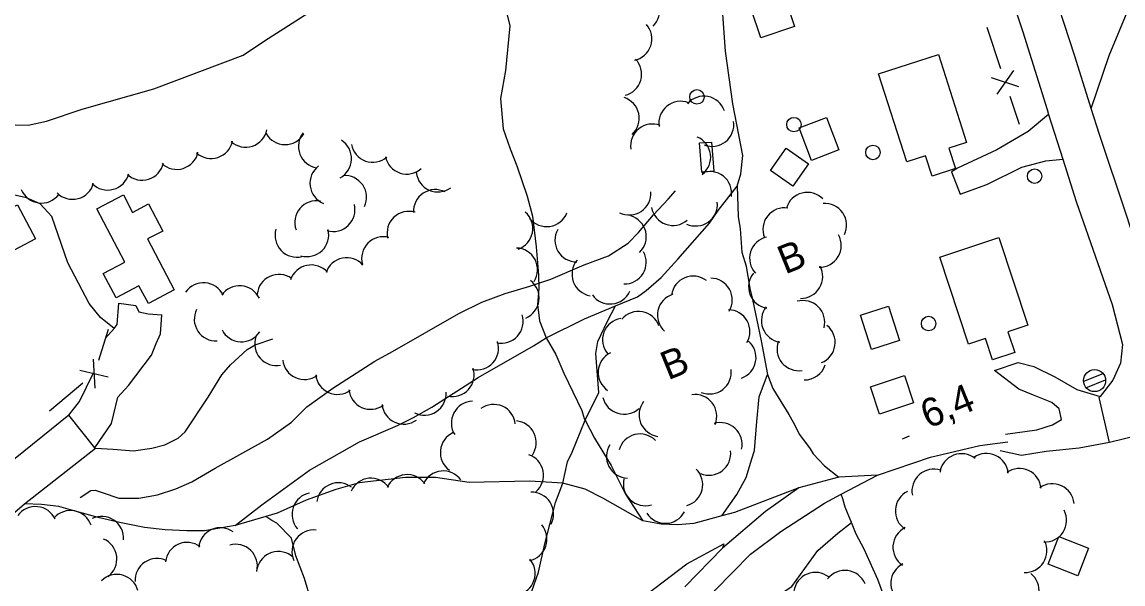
# Model space of a CAD drawing. Extents: x 362852 to 366875, y 5563573 to 5566479.
# Drawn here: x 363726 to 363877.7, y 5565014.1 to 5565091.6 of the extents above; entities that cross this region are included whole.
import ezdxf

# ---------------------------------------------------------------- set-up
doc = ezdxf.new("R2010")
doc.units = 0
for name, color, linetype in [('Niveau 19', 7, 'Continuous'), ('Niveau 2', 7, 'Continuous'), ('Niveau 21', 7, 'Continuous'), ('Niveau 22', 7, 'Continuous'), ('Niveau 3', 7, 'Continuous'), ('Niveau 31', 7, 'Continuous'), ('Niveau 36', 7, 'Continuous'), ('Niveau 37', 7, 'Continuous'), ('Niveau 4', 7, 'Continuous'), ('Niveau 44', 7, 'Continuous')]:
    doc.layers.add(name, color=color, linetype=linetype)

msp = doc.modelspace()

# ---------------------------------------------------------------- linework, layer by layer
at = {"layer": 'Niveau 19'}
for points in [[(363867.43, 5565078.84), (363864.61, 5565076.48), (363860.28, 5565073.95), (363854.89, 5565071.45), (363854.05, 5565070.96), (363855.26, 5565067.86), (363858.91, 5565069.2), (363863.75, 5565071.56), (363867.05, 5565072.44), (363869.37, 5565072.68)], [(363737.49, 5565048.02), (363738.66, 5565049.36), (363739.11, 5565049.87), (363739.34, 5565052.82), (363741.65, 5565052.52), (363742.08, 5565051.63), (363743.37, 5565051.35), (363745.23, 5565051.23)], [(363736.04, 5565032.91), (363738.31, 5565036.25), (363739.2, 5565039.87), (363740.66, 5565041.5), (363743.83, 5565045.65), (363744.47, 5565047.29), (363745.06, 5565048.6), (363745.23, 5565051.23)], [(363861.5, 5565034.77), (363865.81, 5565035.35), (363867.96, 5565036.04), (363869.21, 5565036.81), (363868.9, 5565038.28), (363867.86, 5565039.16), (363865.34, 5565040.13), (363863.31, 5565040.98), (363859.96, 5565043.55), (363863.25, 5565044.65), (363865.38, 5565044.12), (363868.3, 5565042.66), (363871.33, 5565040.93), (363874.52, 5565039.95)], [(363732.42, 5565037.4), (363733.9, 5565039.29), (363735.84, 5565043.22)], [(363875.8, 5565033.63), (363871.63, 5565032.86), (363867.09, 5565032.37), (363863.69, 5565031.85), (363860.75, 5565032.46)]]:
    msp.add_lwpolyline(points, dxfattribs=at)
at = {"layer": 'Niveau 2'}
msp.add_lwpolyline([(363717.82, 5565077.58), (363726.82, 5565077.39), (363729.35, 5565077.93), (363734.29, 5565079.58), (363744.13, 5565082.37), (363756.45, 5565087.04), (363759.39, 5565089), (363767, 5565093.88)], dxfattribs=at)
at = {"layer": 'Niveau 21'}
msp.add_line((363736.04, 5565032.91), (363732.42, 5565037.4), dxfattribs=at)
for points in [[(363894.37, 5565204.95), (363891.04, 5565200.97), (363888.24, 5565197.21), (363884.39, 5565191.81), (363881.5, 5565187.79), (363876.28, 5565178.61), (363871.48, 5565169.6), (363867.57, 5565160.54), (363864.93, 5565154.01), (363864.35, 5565152.4), (363861.97, 5565145.76), (363861.32, 5565143.93), (363859.06, 5565135.24), (363857.7, 5565126.8), (363857.47, 5565121.97), (363857.33, 5565119.17), (363857.74, 5565112.52), (363858.63, 5565107.47), (363859.14, 5565105.67), (363861.56, 5565097.13), (363863.86, 5565090.22), (363867.22, 5565079.52), (363867.43, 5565078.84)], [(363883.7, 5565047.85), (363878.1, 5565065.12), (363874.44, 5565076.07), (363873.31, 5565079.68), (363871.04, 5565086.88), (363867.42, 5565098.03), (363864.62, 5565107.96), (363863.74, 5565114.42), (363863.42, 5565120.83), (363863.8, 5565126.62), (363864.8, 5565133.04), (363866.39, 5565139.79), (363868.43, 5565146.89), (363870.62, 5565152.99), (363873.82, 5565160.62), (363876.87, 5565167.16), (363879.55, 5565172.52)], [(363867.43, 5565078.84), (363869.37, 5565072.68), (363871.21, 5565066.83), (363876.17, 5565052.67), (363877.62, 5565047.13), (363877.32, 5565044.54), (363876.29, 5565042.21), (363874.52, 5565039.95)], [(363915.68, 5565009.77), (363911.22, 5565019.68), (363910.43, 5565021.42), (363908.05, 5565027.38), (363905.36, 5565034.13), (363903.31, 5565037.48), (363901.26, 5565038.83), (363899.31, 5565039.65), (363897.27, 5565039.85), (363895.54, 5565039.83), (363887.77, 5565036.92), (363879.96, 5565034.65), (363875.8, 5565033.63), (363874.4, 5565039.81), (363874.52, 5565039.95)], [(363732.42, 5565037.4), (363723.86, 5565030.46)], [(363716.45, 5565016.72), (363726.33, 5565025.15), (363736.09, 5565032.84), (363736.04, 5565032.91)]]:
    msp.add_lwpolyline(points, dxfattribs=at)
at = {"layer": 'Niveau 22'}
for points in [[(363873.31, 5565079.68), (363875.76, 5565086.97), (363878.5, 5565093.5), (363882.73, 5565099.18), (363884.77, 5565100.7), (363888, 5565103.1), (363895.3, 5565106.25), (363903.87, 5565109.26), (363916.24, 5565113.9), (363922.12, 5565116.64), (363925.51, 5565118.21), (363932.97, 5565122.72), (363938.65, 5565127.79), (363941.22, 5565131.75), (363943.05, 5565134.57), (363945.78, 5565140.62), (363948.22, 5565145.68), (363952.57, 5565150.15), (363955.91, 5565153.28)], [(363792.23, 5565095.08), (363793.2, 5565091.07), (363792.62, 5565084.9), (363791.89, 5565081.03), (363792.28, 5565076.87), (363793.22, 5565074.13), (363794.16, 5565071.75), (363795.59, 5565067.58), (363796.32, 5565064.84), (363796.83, 5565060.58), (363797.14, 5565056.72), (363797.21, 5565054.87), (363797.03, 5565052.66), (363797.27, 5565050.39), (363798.18, 5565048.04), (363799.54, 5565045.75), (363800.65, 5565043.17), (363803.11, 5565038.05), (363803.44, 5565036.94), (363803.56, 5565036.72), (363804.86, 5565034.24), (363807.17, 5565030.43), (363809.12, 5565026.51), (363811.52, 5565022.81)], [(363755.37, 5565022.19), (363759.02, 5565025.03), (363765.61, 5565029.8), (363772.49, 5565033.72), (363777.7, 5565035.95), (363779.93, 5565037.05), (363782.45, 5565038.49), (363788.84, 5565042.58), (363796.46, 5565046.93), (363798.18, 5565048.04), (363803.5, 5565050.66), (363807.76, 5565052.45), (363810.79, 5565053.72), (363812, 5565054.59), (363814.07, 5565056.38), (363816.35, 5565058.88), (363820.7, 5565063.84), (363821.91, 5565065.59), (363824.52, 5565068.97), (363825.01, 5565070.68), (363825.3, 5565073.17), (363823.9, 5565080.32), (363822.89, 5565087.58), (363822.54, 5565092.69)], [(363824.52, 5565068.97), (363824.67, 5565064.78), (363824.93, 5565063.08), (363825.18, 5565059.87), (363825.78, 5565057.93), (363826.26, 5565054.87), (363826.61, 5565053.32), (363827.81, 5565047.62), (363828.68, 5565043.01), (363829.42, 5565041.09), (363831.65, 5565037.47), (363832.22, 5565036.42), (363833.1, 5565034.72), (363834.56, 5565032.76), (363835, 5565032.06), (363836.56, 5565030.39), (363838.53, 5565028.83)], [(363738.66, 5565049.36), (363736.78, 5565050.87), (363735.24, 5565052.8), (363732.28, 5565058.37), (363730.11, 5565064.79), (363728.47, 5565066.53), (363726.62, 5565067.36), (363723.95, 5565067.95)], [(363795.55, 5565011.17), (363797.16, 5565015.74), (363798.02, 5565019.65), (363799.48, 5565025.35), (363800.49, 5565028.01), (363801.13, 5565030.96), (363801.78, 5565032.28), (363803.56, 5565036.72), (363805.47, 5565040.52), (363805.05, 5565045.91), (363805.32, 5565047.56), (363806.66, 5565050.37), (363807.76, 5565052.45)], [(363736.09, 5565032.84), (363738.53, 5565032.69), (363741.36, 5565032.47), (363743.89, 5565032.83), (363745.64, 5565033.29), (363747.49, 5565034.24), (363748.45, 5565035.11), (363751.61, 5565039.87), (363753.53, 5565042.94), (363754.69, 5565044.35), (363757.02, 5565046.46), (363758.13, 5565047.11), (363760.54, 5565047.91)], [(363822.41, 5565023.52), (363824.49, 5565026.46), (363825.75, 5565028.78), (363826.56, 5565031.37), (363826.9, 5565032.51), (363827.21, 5565036.51), (363827.57, 5565039.91), (363828.68, 5565043.01)], [(363821.19, 5565012.89), (363821.5, 5565013.28), (363826.36, 5565018.25), (363830.54, 5565021.35), (363836.53, 5565025.25), (363838.85, 5565026.48), (363843.86, 5565029.13), (363851.14, 5565031.62), (363857.97, 5565033.23), (363861.81, 5565033.71)], [(363843.86, 5565029.13), (363838.53, 5565028.83), (363833.02, 5565027.35), (363824.15, 5565023.99), (363822.41, 5565023.52), (363818.55, 5565022.47), (363816.33, 5565022.28), (363814.06, 5565022.38), (363811.52, 5565022.81), (363805.99, 5565025.95), (363803.58, 5565027.21), (363800.49, 5565028.01), (363795.92, 5565028.29), (363787.59, 5565028.09), (363782.96, 5565028.79), (363778.84, 5565028.79), (363772.46, 5565028.07), (363769.21, 5565027.15), (363765.14, 5565025.66), (363761.15, 5565023.87), (363759.59, 5565023.42), (363755.37, 5565022.19), (363751.14, 5565021.43), (363748.71, 5565021.43), (363745.69, 5565021.59), (363742.88, 5565021.91), (363739.64, 5565022.55), (363736.67, 5565023.24), (363733.3, 5565024.14), (363731.05, 5565024.78), (363728.69, 5565025.06), (363726.33, 5565025.15)], [(363833.02, 5565027.35), (363828.42, 5565024.12), (363822.51, 5565019.07), (363817.3, 5565013.74)], [(363849.05, 5564982.4), (363848.34, 5564985.46), (363847.91, 5564987.31), (363847.39, 5564990.38), (363846.13, 5564994.51), (363844.99, 5564996.92), (363844.32, 5564998.34), (363843.11, 5565000.22), (363842.91, 5565001.33), (363843.72, 5565004.22), (363844.44, 5565006.89), (363845.06, 5565010.61), (363844.84, 5565011.77), (363844.67, 5565012.64), (363843.89, 5565014.73), (363843.25, 5565016.15), (363842.01, 5565018.9), (363840.92, 5565020.99), (363840.27, 5565022.6), (363839.42, 5565024.71), (363839.09, 5565025.86), (363838.85, 5565026.48)], [(363781.38, 5564980.54), (363780.38, 5564983.7), (363779, 5564986.03), (363777.68, 5564989.44), (363777.04, 5564990.35), (363775.24, 5564993.96), (363774.06, 5564995.99), (363772.46, 5564999.15), (363768.75, 5565005.94), (363766.68, 5565010.04), (363765.79, 5565011.92), (363764.9, 5565014.87), (363763.73, 5565018.02), (363763.1, 5565020.43), (363761.08, 5565022.48), (363760.42, 5565022.89), (363759.59, 5565023.42)], [(363821.19, 5565012.89), (363822.8, 5565011.71), (363824.84, 5565011.55), (363826.92, 5565011.59), (363829.27, 5565012.21), (363830.74, 5565012.88), (363832.05, 5565013.79), (363835.63, 5565018.72), (363838.4, 5565021.14), (363840.27, 5565022.6)], [(363785.02, 5564985.98), (363786.23, 5564987.45), (363787.2, 5564988.85), (363789.75, 5564992.37), (363792.35, 5564996.98), (363793.99, 5564998.69), (363795.01, 5564999.89), (363796.13, 5565001.88), (363801.02, 5565006.13), (363802.76, 5565007.25), (363805.53, 5565008.29), (363806.4, 5565008.58), (363808.2, 5565009.82), (363813.16, 5565013.55), (363817.58, 5565016.89), (363822.68, 5565019.67), (363822.51, 5565019.07)]]:
    msp.add_lwpolyline(points, dxfattribs=at)
at = {"layer": 'Niveau 3'}
msp.add_line((363847.29, 5565034.13), (363848.25, 5565034.52), dxfattribs=at)
at = {"layer": 'Niveau 31'}
for points in [[(363832.42, 5565090.99), (363827.79, 5565089.4), (363826.38, 5565093.51), (363831.02, 5565095.1), (363832.42, 5565090.99)], [(363850.48, 5565073.13), (363847.9, 5565072.3), (363844, 5565084.46), (363852.25, 5565087.11), (363856.13, 5565074.99), (363853.67, 5565074.2), (363854.58, 5565071.38), (363851.37, 5565070.35), (363850.48, 5565073.13)], [(363836.83, 5565078.44), (363838.54, 5565073.96), (363834.77, 5565072.52), (363833.06, 5565077.01), (363836.83, 5565078.44)], [(363821, 5565075.04), (363821.29, 5565071.03), (363819.65, 5565070.91), (363819.35, 5565074.92), (363821, 5565075.04)], [(363831.26, 5565074.21), (363834.36, 5565072.04), (363832.18, 5565068.95), (363829.09, 5565071.12), (363831.26, 5565074.21)], [(363725.34, 5565066.41), (363727.82, 5565061.69), (363723.34, 5565059.33), (363720.25, 5565065.2), (363723.76, 5565067.05), (363724.37, 5565065.89), (363725.34, 5565066.41)], [(363736.31, 5565065.84), (363739.95, 5565067.75), (363741.21, 5565065.35), (363743.41, 5565066.51), (363745.37, 5565062.78), (363743.28, 5565061.69), (363746.97, 5565054.65), (363743.39, 5565052.77), (363742.1, 5565055.24), (363738.94, 5565053.58), (363737.18, 5565056.93), (363740.17, 5565058.5), (363736.31, 5565065.84)], [(363858.74, 5565047.96), (363856.4, 5565047.19), (363852.44, 5565059.17), (363860.59, 5565061.87), (363864.58, 5565049.8), (363861.83, 5565048.89), (363862.78, 5565046.01), (363859.72, 5565045), (363858.74, 5565047.96)], [(363845.35, 5565052.41), (363846.89, 5565047.69), (363843.04, 5565046.43), (363841.5, 5565051.16), (363845.35, 5565052.41)], [(363842.87, 5565041.3), (363847.56, 5565042.85), (363848.8, 5565039.1), (363844.11, 5565037.55), (363842.87, 5565041.3)], [(363868.85, 5565020.65), (363872.93, 5565019.07), (363871.46, 5565015.25), (363867.37, 5565016.84), (363868.85, 5565020.65)]]:
    msp.add_lwpolyline(points, dxfattribs=at)
at = {"layer": 'Niveau 36'}
for p, q in [((363874.92, 5565043.11), (363872.24, 5565042.02)), ((363872.58, 5565041.17), (363875.27, 5565042.26))]:
    msp.add_line(p, q, dxfattribs=at)
for centre, radius in [((363818.98, 5565081.27), 1), ((363832.34, 5565077.45), 1), ((363843.23, 5565073.61), 1), ((363865.5, 5565070.34), 1), ((363850.9, 5565050.02), 1), ((363873.76, 5565042.16), 1.52)]:
    msp.add_circle(centre, radius, dxfattribs=at)
at = {"layer": 'Niveau 37'}
for p, q in [((363858.93, 5565090.88), (363860.81, 5565085.18)), ((363863.33, 5565082.65), (363859.54, 5565083.92)), ((363862.58, 5565084.93), (363860.3, 5565081.65)), ((363862.07, 5565081.39), (363863.36, 5565077.49)), ((363736.59, 5565044.97), (363737.88, 5565049.24)), ((363735.79, 5565045.12), (363736.01, 5565041.13)), ((363733.95, 5565043.58), (363737.85, 5565042.67)), ((363729.78, 5565037.98), (363734.37, 5565041.84))]:
    msp.add_line(p, q, dxfattribs=at)
at = {"layer": 'Niveau 4'}
msp.add_lwpolyline([(363733.99, 5565026.03), (363735.46, 5565027.01), (363736.06, 5565027.06), (363737.02, 5565026.71), (363739.32, 5565025.96), (363742.06, 5565025.96), (363744.63, 5565026.39), (363747.16, 5565027.24), (363749.38, 5565028.21), (363752.6, 5565030.09), (363759.83, 5565034.06), (363763.11, 5565036.44), (363765.23, 5565038.56), (363768.81, 5565041.1), (363774.58, 5565044.84), (363777.03, 5565046.16), (363786.18, 5565051.41), (363789.35, 5565052.96), (363792.54, 5565054.15), (363795.93, 5565055.16), (363798.83, 5565056.16), (363803.45, 5565058.12), (363806.81, 5565059.37), (363809.48, 5565061.09), (363810.93, 5565062.57), (363812.98, 5565065.03), (363815.03, 5565067.19), (363816, 5565068.34)], dxfattribs=at)
at = {"layer": 'Niveau 44'}
for centre, start, end in [((363810.84, 5565093.17), 314.1851, 74.163), ((363809.77, 5565089.26), 281.3895, 41.3674), ((363808.35, 5565084.4), 283.9924, 43.9703), ((363808.03, 5565078.32), 312.3077, 72.2856), ((363816.73, 5565077.66), 68.8732, 188.8511), ((363819.92, 5565078.37), 19.0763, 139.0543), ((363821.06, 5565077.44), 248.6067, 8.5847), ((363756.8, 5565077.34), 228.1221, 348.1001), ((363762.23, 5565077.69), 209.5866, 329.5646), ((363767.07, 5565074.45), 141.0323, 261.0102), ((363812.83, 5565074.53), 68.8732, 188.8511), ((363752.05, 5565075.78), 228.1221, 348.1001), ((363768.39, 5565072.74), 297.992, 57.97), ((363774.32, 5565075.25), 190.1599, 310.1379), ((363817.87, 5565072.96), 307.7318, 67.7098), ((363747.3, 5565074.28), 227.4685, 347.4465), ((363742.53, 5565072.78), 227.4685, 347.4465), ((363768.66, 5565069.36), 127.3737, 247.3517), ((363778.99, 5565073.63), 192.1147, 312.0926), ((363737.79, 5565071.43), 224.8228, 344.8008), ((363770.47, 5565067.42), 334.8327, 94.8107), ((363783.29, 5565071.17), 186.3446, 306.3225), ((363820.76, 5565067.98), 351.7063, 111.6843), ((363728.66, 5565069.63), 202.3627, 322.3407), ((363732.95, 5565070.15), 224.8228, 344.8008), ((363782.92, 5565065.49), 63.2366, 183.2145), ((363766.56, 5565063.95), 79.6796, 199.6575), ((363809.65, 5565067.99), 243.5763, 3.5542), ((363834.19, 5565065.11), 44.2281, 164.2061), ((363768.86, 5565065.71), 253.8625, 13.8405), ((363779.28, 5565062.49), 73.2518, 193.2297), ((363815.68, 5565066.55), 190.5415, 310.5194), ((363818.79, 5565066.47), 245.2057, 5.1837), ((363831.06, 5565062.98), 81.5207, 201.4986), ((363836.6, 5565063.57), 334.7052, 94.6831), ((363793.36, 5565063.12), 288.9428, 48.9207), ((363798.28, 5565066.38), 218.2654, 338.2433), ((363809, 5565062), 313.5864, 73.5643), ((363763.85, 5565062.17), 163.6034, 283.5814), ((363765.25, 5565062.25), 253.8625, 13.8405), ((363802.41, 5565061.52), 150.5526, 270.5306), ((363775.78, 5565059), 75.3995, 195.3775), ((363829.23, 5565059.01), 102.6871, 222.665), ((363835.86, 5565060.78), 269.2274, 29.2054), ((363794.01, 5565057.44), 327.7529, 87.7308), ((363808.99, 5565058.48), 268.6483, 28.6263), ((363765.82, 5565055.1), 41.5771, 161.555), ((363770.72, 5565056.1), 41.5771, 161.555), ((363804.76, 5565056.82), 140.2378, 260.2157), ((363833.3, 5565056.49), 269.2274, 29.2054), ((363761.38, 5565053.8), 54.7388, 174.7167), ((363818.45, 5565053.56), 52.3423, 172.3202), ((363829.09, 5565055.09), 140.7453, 260.7232), ((363750.99, 5565052.65), 25.2277, 145.2056), ((363755.97, 5565052.23), 25.2277, 145.2056), ((363794.23, 5565053.55), 292.7156, 52.6935), ((363820.84, 5565053.28), 329.2658, 89.2437), ((363807.02, 5565055.72), 215.4029, 335.3808), ((363816.54, 5565051.19), 107.5435, 227.5215), ((363752.72, 5565050.62), 153.0374, 273.0153), ((363823.28, 5565048.92), 329.2658, 89.2437), ((363830.86, 5565050.42), 140.7453, 260.7232), ((363833.58, 5565050.2), 345.3898, 105.3677), ((363792.03, 5565050.32), 257.5616, 17.5396), ((363808.96, 5565047.77), 99.2958, 219.2737), ((363810.92, 5565048.69), 19.6208, 139.5987), ((363756.21, 5565050.51), 207.3188, 327.2968), ((363835.02, 5565047.42), 291.5986, 51.5765), ((363761.04, 5565047.23), 161.0088, 280.9867), ((363788.65, 5565046.63), 257.5616, 17.5396), ((363824.12, 5565045.34), 289.1913, 49.1692), ((363833.01, 5565046.52), 159.2681, 279.246), ((363808.36, 5565043.28), 115.8202, 235.7981), ((363764.89, 5565045.3), 185.8252, 305.8031), ((363833.8, 5565045.25), 268.7115, 342.4358), ((363769.45, 5565043.25), 185.8252, 305.8031), ((363785.28, 5565042.95), 257.5616, 17.5396), ((363820.71, 5565043.31), 247.4872, 7.4652), ((363774.01, 5565041.2), 185.8252, 305.8031), ((363781.43, 5565040.39), 243.1909, 3.1688), ((363808.95, 5565040.52), 193.1175, 313.0955), ((363818.71, 5565037.24), 338.1694, 98.1473), ((363778.57, 5565039.15), 185.8252, 305.8031), ((363788.14, 5565036.31), 92.0464, 212.0244), ((363790.97, 5565035.87), 6.1007, 126.0787), ((363814, 5565037.44), 142.1568, 262.1348), ((363793.84, 5565033.61), 325.1176, 85.0955), ((363822.2, 5565033.37), 346.9385, 106.9164), ((363786.62, 5565032.25), 114.5626, 234.5405), ((363811.13, 5565031.8), 44.0576, 164.0355), ((363809.51, 5565031.72), 147.7208, 267.6988), ((363820.63, 5565032.11), 247.1846, 7.1625), ((363855.43, 5565029.08), 51.1461, 171.124), ((363858.87, 5565029.12), 5.2951, 125.273), ((363794.83, 5565029.11), 310.9144, 70.8923), ((363779.05, 5565026.2), 35.785, 155.763), ((363784.02, 5565026.7), 35.785, 155.763), ((363816.77, 5565027.82), 285.6646, 45.6425), ((363851.6, 5565026.94), 71.5618, 191.5398), ((363863.41, 5565027.03), 5.2951, 125.273), ((363769.57, 5565025.07), 52.3354, 172.3134), ((363774.07, 5565025.7), 35.785, 155.763), ((363811.84, 5565027.91), 166.5408, 286.5187), ((363867.95, 5565024.94), 5.2951, 125.273), ((363766.18, 5565023.71), 101.1468, 221.1247), ((363796.22, 5565023.77), 332.3563, 92.3342), ((363849.31, 5565024.18), 116.1627, 236.1406), ((363727.83, 5565021.79), 24.4405, 144.4185), ((363732.65, 5565021.24), 18.8304, 138.8083), ((363736.97, 5565020.43), 355.8514, 115.8294), ((363814.61, 5565025.48), 212.0914, 332.0693), ((363866.9, 5565022.9), 267.3091, 27.2871), ((363753.32, 5565018.87), 53.8023, 173.7803), ((363766.18, 5565018.56), 83.7168, 203.6948), ((363795.32, 5565020.29), 280.9993, 40.9772), ((363848.98, 5565019.19), 116.1627, 236.1406), ((363736.05, 5565017.55), 307.1284, 67.1064), ((363864.2, 5565018.7), 267.3091, 27.2871), ((363748.74, 5565016.85), 53.8023, 173.7803), ((363755.41, 5565016.6), 345.6938, 105.6717), ((363761.31, 5565015.59), 47.5222, 167.5001), ((363744.57, 5565014.63), 63.5334, 183.5113), ((363793.69, 5565015.56), 280.9993, 40.9772), ((363848.69, 5565014.21), 116.749, 236.7269), ((363739.05, 5565012.44), 14.7459, 134.7238), ((363835.3, 5565012.71), 52.2947, 172.2726), ((363839.37, 5565012.99), 22.6459, 142.6238), ((363863.12, 5565013.2), 292.0258, 52.0038)]:
    msp.add_arc(centre, 3, start, end, dxfattribs=at)

# ---------------------------------------------------------------- texts
at = {"layer": 'Niveau 3'}
msp.add_text('6,4  ', height=3.93, rotation=22.09, dxfattribs=at).set_placement((363850.8, 5565035.49))
at = {"layer": 'Niveau 44'}
for p in [(363831.12, 5565056.76), (363814.99, 5565042.17)]:
    msp.add_text('B', height=3.93, rotation=22.09, dxfattribs=at).set_placement(p)

doc.saveas('drawing.dxf')
